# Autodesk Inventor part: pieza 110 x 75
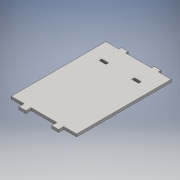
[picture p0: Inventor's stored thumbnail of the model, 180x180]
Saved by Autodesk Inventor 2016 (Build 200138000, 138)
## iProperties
Created: 2016-06
Part Number: pieza 110 x 75
Material: Genérico
Document SubType Name: Modeling
Designer: adm
Density: 1 g/cm^3
Appearance: Valor por defecto
Author: adm
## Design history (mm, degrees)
sketch "Boceto1"
  geometry: L1 (0, 0)-(0, 110); L2 (0, 110)-(15, 110); L3 (15, 110)-(15, 113); L4 (15, 113)-(23, 113); L5 (23, 113)-(23, 110); L6 (23, 110)-(53, 110); L7 (53, 110)-(53, 113); L8 (53, 113)-(61, 113); L9 (61, 113)-(61, 110); L10 (61, 110)-(76, 110); L11 (76, 110)-(76, 0); L12 (76, 0)-(61, 0); L13 (61, 0)-(61, -6); L14 (61, -6)-(53, -6); L15 (53, -6)-(53, 0); L16 (53, 0)-(23, 0); L17 (23, 0)-(23, -6); L18 (23, -6)-(15, -6); L19 (15, -6)-(15, 0); L20 (15, 0)-(0, 0); L21 (15, 90)-(23, 90); L22 (23, 90)-(23, 87); L23 (23, 87)-(15, 87); L24 (15, 87)-(15, 90); L25 (53, 90)-(61, 90); L26 (61, 90)-(61, 87); L27 (61, 87)-(53, 87); L28 (53, 87)-(53, 90)
  constraints: 56 end point, 14 point on line, 9 perpendicular, 1 vertical
extrude "Extrusión1" new body sketch "Boceto1" distance "d26" = 3; taper "d27" = 0 deg
node "Sólido1"
